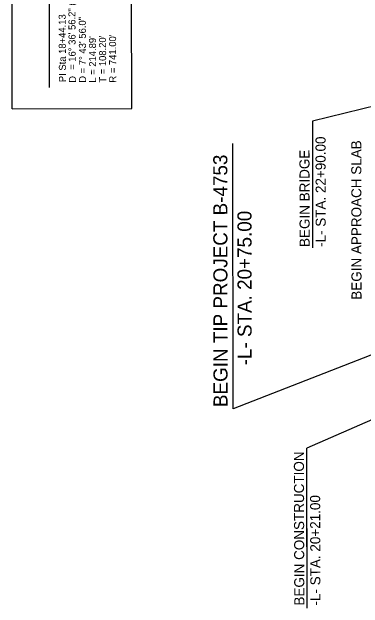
# Model space of a CAD drawing. Extents: x 1373164 to 1374172, y 550391 to 553180.
# Drawn here: x 1373164 to 1373513, y 551106 to 551698 of the extents above; entities that cross this region are included whole.
import ezdxf

# ---------------------------------------------------------------- set-up
doc = ezdxf.new("R2010")
doc.units = 0
for name, color, linetype in [('Exist Structure Minor Pipes RCP 18 Inch Cogo Number', 7, 'Continuous'), ('Exist Structure Minor Pipes RCP 18 Inch Cogo Point CELL', 7, 'Continuous'), ('Exist Utilities Sanitary Sewer Manhole Cogo Elevation', 7, 'Continuous')]:
    doc.layers.add(name, color=color, linetype=linetype)

msp = doc.modelspace()

# ---------------------------------------------------------------- linework, layer by layer
at = {"layer": 'Exist Structure Minor Pipes RCP 18 Inch Cogo Number'}
for p, q in [((1373164.01, 551601.84), (1373163.69, 551969.36)), ((1373282.69, 551601.95), (1373282.36, 551969.46)), ((1373201, 551622.99), (1373200.71, 551952.47)), ((1373164.01, 551601.84), (1373282.69, 551601.95)), ((1373730.51, 551383.91), (1373456.76, 551264.88))]:
    msp.add_line(p, q, dxfattribs=at)
at = {"layer": 'Exist Utilities Sanitary Sewer Manhole Cogo Elevation'}
for p, q in [((1373716.63, 551652.55), (1373462.35, 551589.41)), ((1373462.35, 551589.41), (1373462.46, 551463.6)), ((1373457.19, 551106), (1373456.76, 551264.88)), ((1373457.19, 551106), (1373456.86, 551227.31))]:
    msp.add_line(p, q, dxfattribs=at)
msp.add_lwpolyline([(1373727.72, 551437.84), (1373383.63, 551303.77), (1373383.35, 551567.48)], dxfattribs=at)

# ---------------------------------------------------------------- texts
at = {"layer": 'Exist Structure Minor Pipes RCP 18 Inch Cogo Number'}
for s, height, rotation, p in [('-L- STA. 22+90.00', 10, 90.09502, (1373475.54, 551464.64)), ('BEGIN APPROACH SLAB', 10, 90.09502, (1373511.11, 551412.23)), ('BEGIN BRIDGE', 10, 90.09502, (1373459.54, 551464.61)), ('BEGIN TIP PROJECT B-4753', 14, 90.0612, (1373377.98, 551305.61)), ('-L- STA. 20+75.00', 14, 90.0612, (1373401.93, 551347.06)), ('BEGIN CONSTRUCTION', 10, 90.15672, (1373454.27, 551108.52)), ('-L- STA. 20+21.00', 10, 90.15672, (1373470.27, 551108.57))]:
    msp.add_text(s, height=height, rotation=rotation, dxfattribs=at).set_placement(p)
at = {"layer": 'Exist Structure Minor Pipes RCP 18 Inch Cogo Point CELL'}
for s, p in [('= 16%%d 36\' 56.2" (RT)', (1373227.05, 551640.49)), ('PI Sta 18+44.13', (1373217.4, 551628.27)), ('D = 7%%d 43\' 56.0"', (1373237.4, 551627.69)), ("R = 741.00'", (1373267.4, 551627.82)), ("L = 214.89'", (1373247.4, 551627.73)), ("T = 108.20'", (1373257.4, 551627.77)), ('D', (1373227.4, 551627.64))]:
    msp.add_text(s, height=7, rotation=90.24803, dxfattribs=at).set_placement(p)

doc.saveas('drawing.dxf')
